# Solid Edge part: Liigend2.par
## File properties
Author: Türk
Template: Iso Part.par
Last saved by: Türk
Revision: 6
Application: Solid Edge
Accuracy: 0,990
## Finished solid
Body 1: solid body, 58 faces, 121 edges, 66 vertices.
  Faces by surface: plane 28, torus 16, cylinder 14
  Edges by curve: line 53, circle 52, intersection 16
Bounding box of the edges (mm; curved faces can reach further): 194.330 x 38.000 x 129.102, from (-74.3301, -19, -25) to (120, 19, 104.1025).
Cylindrical faces by radius (mm): R10.5 x3, R20 x2, R25 x1, R25.5 x4, R30.5 x4
Toroidal faces (ring radius, tube radius in mm): R11 r0.5 x6, R19.5 r0.5 x3, R20.5 r0.5 x4, R24.5 r0.5 x1, R25.5 r0.5 x2
Planar faces by outward normal: +y 7, +z 2, -y 7, -z 1, oblique 11
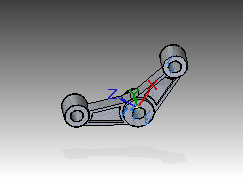
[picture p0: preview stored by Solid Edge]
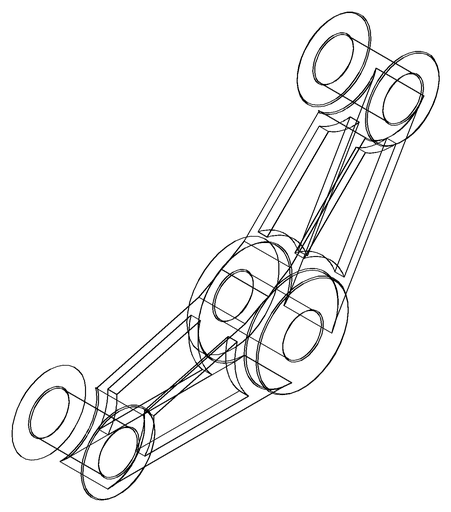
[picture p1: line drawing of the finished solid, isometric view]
